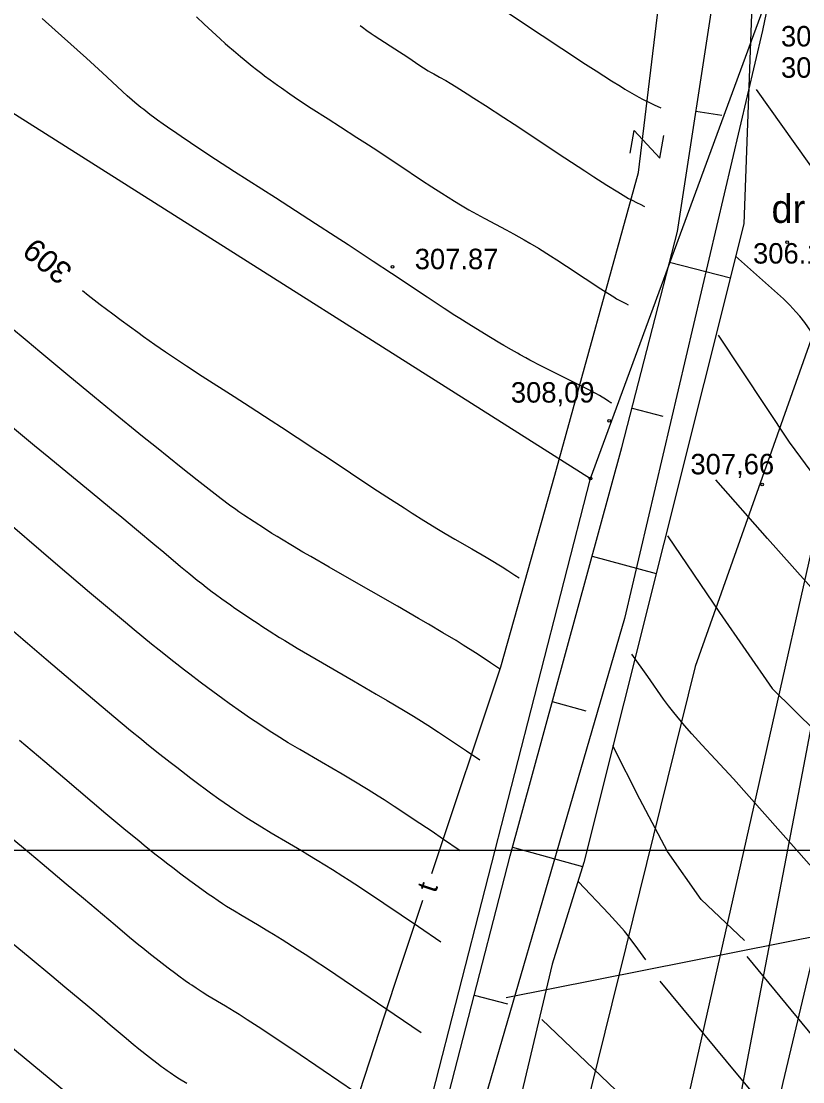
# Model space of a CAD drawing. Extents: x 7477803 to 7478145, y 5500698 to 5500984.
# Drawn here: x 7478000.31 to 7478026.29, y 5500742.3 to 5500777.55 of the extents above; entities that cross this region are included whole.
import ezdxf

# ---------------------------------------------------------------- set-up
doc = ezdxf.new("R2010")
doc.units = 0
for name, color, linetype in [('203-Punkt załamania granicy działki nie stabilizowany', 7, 'Continuous'), ('e_Proj', 7, 'Continuous'), ('eNN', 7, 'Continuous'), ('gr_dzialki', 7, 'Continuous'), ('gr_klasy', 7, 'Continuous'), ('gr_uzytek', 7, 'Continuous'), ('k', 7, 'Continuous'), ('k_rzedne', 7, 'Continuous'), ('opis_uzytek', 7, 'Continuous'), ('pkt_wys', 7, 'Continuous'), ('przehaczenie', 7, 'Continuous'), ('robocza49', 7, 'Continuous'), ('rowy', 7, 'Continuous'), ('skarp_wypel', 7, 'Continuous'), ('skarpa_gora', 7, 'Continuous'), ('t', 7, 'Continuous'), ('t_opisy', 7, 'Continuous'), ('w', 7, 'Continuous'), ('warst_ciagla', 7, 'Continuous'), ('warst_opis', 7, 'Continuous'), ('warst_pogrub', 7, 'Continuous'), ('warst_przeryw', 7, 'Continuous')]:
    doc.layers.add(name, color=color, linetype=linetype)

# ---------------------------------------------------------------- blocks, each defined once
blk = doc.blocks.new('203')
blk.add_circle((0, 0), 0.045)
blk = doc.blocks.new('140')
at = {"layer": 'pkt_wys'}
blk.add_circle((0, 0), 0.045, dxfattribs=at)
blk.add_circle((0, 0), 0.045, dxfattribs=at)
blk = doc.blocks.new('991_5_1')
at = {"layer": 'przehaczenie'}
blk.add_lwpolyline([(-0.38, 0.5), (0.38, 0.5), (-0.38, -0.5), (0.38, -0.5)], dxfattribs=at)

msp = doc.modelspace()

# ---------------------------------------------------------------- linework, layer by layer
at = {"layer": 'e_Proj'}
msp.add_lwpolyline([(7478085.721, 5500828.46), (7478062.59, 5500828.394), (7478057.723, 5500828.457), (7478045.093, 5500816.16), (7478029.949, 5500801.309), (7478024.948, 5500777.245), (7478020.357, 5500757.697), (7478013.921, 5500735.554), (7478010.536, 5500720.256)], dxfattribs=at)
at = {"layer": 'eNN'}
msp.add_lwpolyline([(7478021.084, 5500721.798), (7478022.348, 5500727.709), (7478025.636, 5500742.267), (7478028.577, 5500754.673), (7478031.014, 5500765.159)], dxfattribs=at)
at = {"layer": 'gr_dzialki'}
for points in [[(7477965.87, 5500796.14), (7478019.23, 5500762.35)], [(7478009.6, 5500724.81), (7478019.23, 5500762.35)]]:
    msp.add_lwpolyline(points, dxfattribs=at)
at = {"layer": 'gr_klasy'}
for points in [[(7478019.23, 5500762.35), (7478025.09, 5500778.3)], [(7478009.6, 5500724.81), (7478019.23, 5500762.35)]]:
    msp.add_lwpolyline(points, dxfattribs=at)
at = {"layer": 'gr_uzytek'}
msp.add_lwpolyline([(7478030.57, 5500778.31), (7478022.71, 5500756.1), (7478014.63, 5500723.4), (7478013.163, 5500719.326)], dxfattribs=at)
at = {"layer": 'k'}
msp.add_line((7478029.096, 5500771.195), (7478020.147, 5500731.456), dxfattribs=at)
at = {"layer": 'robocza49'}
msp.add_line((7478000, 5500750), (7478063.045, 5500750), dxfattribs=at)
at = {"layer": 'rowy'}
msp.add_line((7478016.422, 5500745.094), (7478036.731, 5500749.125), dxfattribs=at)
at = {"layer": 'skarp_wypel'}
for p, q in [((7478022.735, 5500774.561), (7478023.594, 5500774.428)), ((7478021.857, 5500769.544), (7478023.88, 5500769.024)), ((7478020.61, 5500764.687), (7478021.635, 5500764.423)), ((7478019.286, 5500759.771), (7478021.412, 5500759.188)), ((7478017.96, 5500754.933), (7478019.077, 5500754.627)), ((7478016.635, 5500750.095), (7478018.966, 5500749.456)), ((7478015.364, 5500745.175), (7478016.47, 5500744.89))]:
    msp.add_line(p, q, dxfattribs=at)
at = {"layer": 'skarpa_gora'}
for points in [[(7478024.881, 5500786.965), (7478024.924, 5500787.202), (7478024.325, 5500770.813), (7478019.007, 5500749.589), (7478017.956, 5500746.211), (7478015.629, 5500736.387), (7478013.818, 5500729.802), (7478010.366, 5500720.316)], [(7478008.529, 5500720.966), (7478013.614, 5500738.374), (7478016.556, 5500749.806), (7478020.275, 5500763.382), (7478022.118, 5500770.559), (7478023.375, 5500778.71), (7478024.881, 5500786.965)]]:
    msp.add_lwpolyline(points, dxfattribs=at)
at = {"layer": 't'}
for points in [[(7478013.952, 5500749.22), (7478016.25, 5500756.094), (7478018.043, 5500762.466), (7478020.822, 5500772.519), (7478021.714, 5500779.89), (7478022.482, 5500781.51), (7478023.011, 5500782.131), (7478024.071, 5500782.682), (7478025.381, 5500782.734), (7478026.491, 5500782.665), (7478029.072, 5500781.778), (7478030.398, 5500780.809)], [(7478005.519, 5500722.031), (7478006.224, 5500724.533), (7478008.555, 5500732.765), (7478012.721, 5500745.54), (7478013.655, 5500748.332)]]:
    msp.add_lwpolyline(points, dxfattribs=at)
at = {"layer": 'w'}
msp.add_lwpolyline([(7478028.928, 5500766.534), (7478026.087, 5500751.628), (7478024.78, 5500744.808), (7478022.827, 5500734.611), (7478021.568, 5500727.759), (7478020.307, 5500723.115), (7478018.729, 5500717.357)], dxfattribs=at)
at = {"layer": 'warst_ciagla'}
for points in [[(7478019.944, 5500764.854), (7478019.908, 5500764.872), (7478019.84, 5500764.912), (7478019.726, 5500764.987), (7478019.614, 5500765.057), (7478019.527, 5500765.108), (7478019.406, 5500765.175), (7478019.192, 5500765.288), (7478019.061, 5500765.355), (7478018.837, 5500765.469), (7478018.485, 5500765.645), (7478018.285, 5500765.744), (7478017.842, 5500765.965), (7478017.6, 5500766.088), (7478017.213, 5500766.29), (7478017.078, 5500766.362), (7478016.894, 5500766.464), (7478016.801, 5500766.516), (7478016.609, 5500766.624), (7478016.347, 5500766.776), (7478016.212, 5500766.855), (7478015.901, 5500767.04), (7478015.413, 5500767.339), (7478015.189, 5500767.479), (7478014.881, 5500767.673), (7478014.724, 5500767.774), (7478014.363, 5500768.008), (7478013.801, 5500768.377), (7478012.619, 5500769.164), (7478012.006, 5500769.57), (7478011.17, 5500770.119), (7478010.744, 5500770.397), (7478010.094, 5500770.819), (7478009.208, 5500771.39), (7478008.756, 5500771.679), (7478007.4, 5500772.546), (7478006.76, 5500772.959), (7478006.173, 5500773.345), (7478005.93, 5500773.508), (7478005.624, 5500773.716), (7478005.478, 5500773.816), (7478005.169, 5500774.033), (7478005.023, 5500774.136), (7478004.839, 5500774.269), (7478004.751, 5500774.334), (7478004.584, 5500774.458), (7478004.378, 5500774.616), (7478004.283, 5500774.69), (7478004.086, 5500774.85), (7478003.997, 5500774.925), (7478003.831, 5500775.07), (7478003.672, 5500775.215), (7478003.328, 5500775.538), (7478003.006, 5500775.837), (7478002.474, 5500776.324), (7478002.165, 5500776.605), (7478001.441, 5500777.257), (7478001.004, 5500777.649)], [(7478011.578, 5500777.414), (7478011.647, 5500777.357), (7478011.792, 5500777.247), (7478011.94, 5500777.143), (7478012.038, 5500777.079), (7478012.223, 5500776.96), (7478012.722, 5500776.638), (7478013.155, 5500776.354), (7478013.557, 5500776.087), (7478013.681, 5500776.007), (7478013.838, 5500775.909), (7478013.912, 5500775.863), (7478014.019, 5500775.8), (7478014.152, 5500775.724), (7478014.215, 5500775.69), (7478014.417, 5500775.582), (7478014.564, 5500775.497), (7478014.768, 5500775.372), (7478015.133, 5500775.142), (7478015.356, 5500775), (7478015.74, 5500774.751), (7478016.346, 5500774.355), (7478016.688, 5500774.129), (7478018.38, 5500773.01), (7478019.042, 5500772.576), (7478019.343, 5500772.38), (7478019.769, 5500772.107), (7478020.133, 5500771.878), (7478020.314, 5500771.769), (7478020.497, 5500771.665), (7478020.589, 5500771.614), (7478020.778, 5500771.515), (7478020.875, 5500771.468), (7478021.023, 5500771.399)], [(7478037.23, 5500752.292), (7478035.533, 5500754.662), (7478033.837, 5500757.031), (7478030.597, 5500761.551), (7478027.356, 5500766.07), (7478026.557, 5500767.248), (7478026.349, 5500767.535), (7478026.186, 5500767.744), (7478026.058, 5500767.896), (7478025.857, 5500768.115), (7478025.642, 5500768.321), (7478024.845, 5500769.032), (7478024.048, 5500769.742)], [(7478002.344, 5500768.601), (7478002.53, 5500768.451), (7478002.929, 5500768.14), (7478003.348, 5500767.822), (7478003.63, 5500767.612), (7478004.181, 5500767.211), (7478004.377, 5500767.071), (7478004.751, 5500766.807), (7478005.107, 5500766.56), (7478005.338, 5500766.403), (7478005.797, 5500766.097), (7478006.321, 5500765.756), (7478007.383, 5500765.076), (7478007.913, 5500764.736), (7478008.613, 5500764.283), (7478008.961, 5500764.056), (7478009.481, 5500763.717), (7478010.168, 5500763.264), (7478010.509, 5500763.037), (7478011.996, 5500762.046), (7478012.455, 5500761.745), (7478013.031, 5500761.372), (7478013.303, 5500761.199), (7478013.692, 5500760.954), (7478014.175, 5500760.658), (7478014.401, 5500760.523), (7478014.72, 5500760.335), (7478015.286, 5500760.009), (7478015.764, 5500759.733), (7478015.986, 5500759.602), (7478016.187, 5500759.481), (7478016.297, 5500759.413), (7478016.487, 5500759.291), (7478016.718, 5500759.137), (7478016.853, 5500759.045)], [(7478034.133, 5500748.935), (7478033.014, 5500750.407), (7478031.894, 5500751.88), (7478029.426, 5500755.195), (7478028.164, 5500756.83), (7478027.512, 5500757.63), (7478026.839, 5500758.413), (7478025.117, 5500760.359), (7478023.396, 5500762.305)], [(7477999.108, 5500758.074), (7478001.137, 5500756.346), (7478002.244, 5500755.403), (7478002.818, 5500754.917), (7478003.388, 5500754.439), (7478003.668, 5500754.206), (7478003.943, 5500753.979), (7478004.301, 5500753.687), (7478004.476, 5500753.545), (7478004.819, 5500753.269), (7478005.262, 5500752.919), (7478005.477, 5500752.751), (7478005.944, 5500752.393), (7478006.169, 5500752.223), (7478006.461, 5500752.006), (7478006.604, 5500751.902), (7478006.881, 5500751.703), (7478007.236, 5500751.454), (7478007.406, 5500751.337), (7478007.775, 5500751.092), (7478007.951, 5500750.979), (7478008.289, 5500750.77), (7478008.611, 5500750.576), (7478009.225, 5500750.217), (7478009.627, 5500749.979), (7478009.831, 5500749.857), (7478010.148, 5500749.664), (7478010.658, 5500749.348), (7478011.001, 5500749.131), (7478011.206, 5500748.999), (7478011.581, 5500748.753), (7478012.364, 5500748.231), (7478013.508, 5500747.455), (7478014.251, 5500746.948)], [(7478028.138, 5500747.675), (7478026.06, 5500750.018), (7478023.983, 5500752.362), (7478023.386, 5500753.014), (7478022.933, 5500753.498), (7478022.597, 5500753.865), (7478022.351, 5500754.144), (7478021.994, 5500754.573), (7478021.824, 5500754.794), (7478021.659, 5500755.019), (7478021.133, 5500755.764), (7478020.607, 5500756.509)], [(7478024.344, 5500746.993), (7478022.912, 5500748.355), (7478021.785, 5500749.947), (7478020.867, 5500751.696), (7478019.967, 5500753.459)], [(7478011.649, 5500734.85), (7478008.326, 5500737.122), (7478007.088, 5500737.967), (7478005.947, 5500738.743), (7478005.498, 5500739.046), (7478004.968, 5500739.4), (7478004.67, 5500739.589), (7478004.599, 5500739.636), (7478004.494, 5500739.711), (7478004.438, 5500739.753), (7478004.348, 5500739.823), (7478004.219, 5500739.926), (7478004.15, 5500739.983), (7478003.614, 5500740.431), (7478002.063, 5500741.714), (7477999.307, 5500743.984), (7477995.668, 5500746.981), (7477994.123, 5500748.258), (7477993.37, 5500748.883), (7477992.227, 5500749.834), (7477990.687, 5500751.121), (7477990, 5500751.698), (7477989.207, 5500752.369)], [(7478011.909, 5500741.611), (7478010.345, 5500742.676), (7478009.335, 5500743.36), (7478008.886, 5500743.661), (7478008.303, 5500744.046), (7478007.823, 5500744.355), (7478007.553, 5500744.527), (7478007.39, 5500744.628), (7478007.096, 5500744.808), (7478006.514, 5500745.157), (7478006.322, 5500745.277), (7478006.222, 5500745.34), (7478006.12, 5500745.408), (7478005.979, 5500745.503), (7478005.906, 5500745.553), (7478005.757, 5500745.657), (7478005.549, 5500745.806), (7478005.442, 5500745.885), (7478005.191, 5500746.073), (7478004.792, 5500746.381), (7478004.605, 5500746.529), (7478004.348, 5500746.735), (7478004.216, 5500746.842), (7478003.909, 5500747.094), (7478003.426, 5500747.498), (7478002.375, 5500748.389), (7478001.807, 5500748.869), (7478001.005, 5500749.543), (7478000.585, 5500749.894), (7477999.932, 5500750.439)]]:
    msp.add_lwpolyline(points, dxfattribs=at)
at = {"layer": 'warst_pogrub'}
for points in [[(7477999.886, 5500764.173), (7478000.754, 5500763.45), (7478001.231, 5500763.056), (7478002.043, 5500762.39), (7478002.602, 5500761.932), (7478003.311, 5500761.347), (7478003.65, 5500761.067), (7478004.138, 5500760.66), (7478004.752, 5500760.145), (7478005.044, 5500759.9), (7478005.602, 5500759.429), (7478005.879, 5500759.199), (7478006.161, 5500758.971), (7478006.306, 5500758.857), (7478006.454, 5500758.742), (7478006.656, 5500758.588), (7478006.76, 5500758.511), (7478006.971, 5500758.356), (7478007.262, 5500758.148), (7478007.412, 5500758.043), (7478007.757, 5500757.806), (7478007.935, 5500757.687), (7478008.178, 5500757.527), (7478008.301, 5500757.447), (7478008.553, 5500757.286), (7478008.897, 5500757.07), (7478009.073, 5500756.961), (7478009.479, 5500756.715), (7478009.686, 5500756.591), (7478010.108, 5500756.344), (7478011.354, 5500755.626), (7478012.11, 5500755.187), (7478012.472, 5500754.973), (7478013.013, 5500754.65), (7478013.346, 5500754.449), (7478013.526, 5500754.337), (7478013.828, 5500754.146), (7478014.181, 5500753.918), (7478014.382, 5500753.785), (7478014.844, 5500753.478), (7478015.108, 5500753.299), (7478015.552, 5500752.996)], [(7478021.067, 5500746.354), (7478020.717, 5500746.833), (7478020.54, 5500747.07), (7478020.448, 5500747.187), (7478020.355, 5500747.302), (7478020.173, 5500747.514), (7478019.843, 5500747.877), (7478018.828, 5500748.943)], [(7478027.721, 5500738.329), (7478026.825, 5500739.318), (7478026.384, 5500739.82), (7478025.952, 5500740.329), (7478023.747, 5500742.986), (7478021.542, 5500745.643)]]:
    msp.add_lwpolyline(points, dxfattribs=at)
at = {"layer": 'warst_przeryw'}
for points in [[(7478016.304, 5500777.954), (7478017.624, 5500777.075), (7478018.278, 5500776.643), (7478019.06, 5500776.131), (7478019.418, 5500775.9), (7478019.928, 5500775.574), (7478020.223, 5500775.39), (7478020.371, 5500775.299), (7478020.598, 5500775.165), (7478020.834, 5500775.032), (7478020.957, 5500774.967), (7478021.214, 5500774.836), (7478021.35, 5500774.77), (7478021.563, 5500774.672)], [(7478006.131, 5500777.702), (7478006.391, 5500777.454), (7478006.652, 5500777.21), (7478006.783, 5500777.089), (7478006.915, 5500776.97), (7478007.092, 5500776.813), (7478007.18, 5500776.735), (7478007.358, 5500776.581), (7478007.597, 5500776.38), (7478007.717, 5500776.281), (7478007.988, 5500776.061), (7478008.125, 5500775.953), (7478008.308, 5500775.812), (7478008.399, 5500775.742), (7478008.584, 5500775.604), (7478008.831, 5500775.423), (7478008.955, 5500775.334), (7478009.236, 5500775.138), (7478009.378, 5500775.042), (7478009.662, 5500774.853), (7478009.946, 5500774.668), (7478010.51, 5500774.307), (7478010.925, 5500774.04), (7478011.467, 5500773.691), (7478011.733, 5500773.518), (7478012.125, 5500773.262), (7478012.636, 5500772.925), (7478012.887, 5500772.759), (7478013.614, 5500772.275), (7478013.96, 5500772.047), (7478014.291, 5500771.834), (7478014.708, 5500771.573), (7478014.906, 5500771.452), (7478015.191, 5500771.283), (7478015.312, 5500771.213), (7478015.47, 5500771.124), (7478015.546, 5500771.081), (7478015.714, 5500770.99), (7478016.425, 5500770.62), (7478016.673, 5500770.485), (7478017.025, 5500770.286), (7478017.209, 5500770.177), (7478017.496, 5500770.004), (7478017.898, 5500769.753), (7478018.108, 5500769.619), (7478018.43, 5500769.409), (7478019.053, 5500768.999), (7478019.574, 5500768.658), (7478019.805, 5500768.51), (7478020.001, 5500768.386), (7478020.099, 5500768.327), (7478020.249, 5500768.243), (7478020.403, 5500768.164), (7478020.484, 5500768.127)], [(7478024.737, 5500775.282), (7478028.185, 5500770.437), (7478030.56, 5500764.878), (7478033.801, 5500759.808), (7478037.328, 5500754.935)], [(7478016.203, 5500756.021), (7478015.91, 5500756.22), (7478015.732, 5500756.34), (7478015.41, 5500756.552), (7478015, 5500756.815), (7478014.761, 5500756.963), (7478014.326, 5500757.225), (7478013.846, 5500757.508), (7478013.517, 5500757.7), (7478012.813, 5500758.106), (7478011.062, 5500759.106), (7478010.54, 5500759.405), (7478009.935, 5500759.754), (7478009.671, 5500759.908), (7478009.326, 5500760.111), (7478008.956, 5500760.331), (7478008.81, 5500760.42), (7478008.637, 5500760.528), (7478008.389, 5500760.691), (7478008.05, 5500760.914), (7478007.705, 5500761.137), (7478007.539, 5500761.245), (7478007.436, 5500761.316), (7478007.233, 5500761.463), (7478006.953, 5500761.674), (7478006.455, 5500762.061), (7478006.151, 5500762.301), (7478005.629, 5500762.717), (7478004.806, 5500763.377), (7478004.34, 5500763.753), (7478003.307, 5500764.593), (7478002.746, 5500765.052), (7478001.86, 5500765.782), (7478000.93, 5500766.557), (7478000.503, 5500766.915), (7477999.922, 5500767.405)], [(7478023.475, 5500767.116), (7478025.833, 5500763.558), (7478028.366, 5500760.127), (7478030.951, 5500756.73), (7478033.451, 5500753.27)], [(7478014.902, 5500749.972), (7478014.308, 5500750.377), (7478013.962, 5500750.612), (7478013.373, 5500751.008), (7478013.125, 5500751.174), (7478012.704, 5500751.45), (7478012.366, 5500751.668), (7478012.174, 5500751.79), (7478011.836, 5500751.999), (7478011.31, 5500752.319), (7478010.971, 5500752.522), (7478010.289, 5500752.921), (7478009.567, 5500753.341), (7478009.184, 5500753.569), (7478008.785, 5500753.814), (7478008.578, 5500753.945), (7478008.367, 5500754.082), (7478008.079, 5500754.273), (7478007.931, 5500754.373), (7478007.63, 5500754.58), (7478007.216, 5500754.873), (7478007.004, 5500755.026), (7478006.512, 5500755.389), (7478006.259, 5500755.58), (7478005.914, 5500755.843), (7478005.739, 5500755.978), (7478005.382, 5500756.257), (7478004.893, 5500756.646), (7478004.643, 5500756.847), (7478004.067, 5500757.318), (7478003.772, 5500757.562), (7478003.175, 5500758.061), (7478002.58, 5500758.564), (7478001.446, 5500759.531), (7477999.454, 5500761.229)], [(7478021.789, 5500760.44), (7478023.517, 5500757.897), (7478025.268, 5500755.372), (7478027.456, 5500753.206), (7478029.913, 5500751.319)], [(7478013.601, 5500743.923), (7478012.708, 5500744.533), (7478011.354, 5500745.454), (7478010.458, 5500746.057), (7478010.046, 5500746.33), (7478009.829, 5500746.472), (7478009.48, 5500746.697), (7478008.985, 5500747.01), (7478008.692, 5500747.192), (7478008.509, 5500747.304), (7478008.161, 5500747.513), (7478007.657, 5500747.81), (7478007.401, 5500747.963), (7478007.136, 5500748.128), (7478006.999, 5500748.216), (7478006.857, 5500748.31), (7478006.661, 5500748.441), (7478006.56, 5500748.511), (7478006.353, 5500748.656), (7478006.065, 5500748.863), (7478005.916, 5500748.972), (7478005.567, 5500749.233), (7478005.387, 5500749.371), (7478005.14, 5500749.562), (7478005.013, 5500749.661), (7478004.754, 5500749.865), (7478004.398, 5500750.152), (7478004.214, 5500750.301), (7478003.789, 5500750.65), (7478003.122, 5500751.208), (7478002.666, 5500751.593), (7478001.756, 5500752.368), (7478001.095, 5500752.929), (7478000.252, 5500753.642)], [(7478005.814, 5500742.237), (7478005.567, 5500742.388), (7478005.446, 5500742.464), (7478005.253, 5500742.594), (7478005.161, 5500742.658), (7478005.034, 5500742.75), (7478004.968, 5500742.798), (7478004.814, 5500742.913), (7478004.57, 5500743.102), (7478004.217, 5500743.384), (7478004.029, 5500743.539), (7478003.73, 5500743.789), (7478003.267, 5500744.18), (7478002.994, 5500744.41), (7478002.519, 5500744.809), (7478001.759, 5500745.443), (7478001.324, 5500745.804), (7478000.605, 5500746.4), (7477999.52, 5500747.297)], [(7478034.445, 5500735.155), (7478031.806, 5500737.855), (7478029.286, 5500740.667), (7478026.843, 5500743.549), (7478024.438, 5500746.459)], [(7478032.47, 5500728.495), (7478028.924, 5500732.62), (7478025.371, 5500736.739), (7478021.544, 5500740.607), (7478017.614, 5500744.368)]]:
    msp.add_lwpolyline(points, dxfattribs=at)

# ---------------------------------------------------------------- block references
at = {"layer": '203-Punkt załamania granicy działki nie stabilizowany'}
msp.add_blockref('203', (7478019.23, 5500762.35), dxfattribs=at)
at = {"layer": 'pkt_wys', "rotation": 0.0626175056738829}
for p in [(7478025.768, 5500770.212), (7478012.651, 5500769.385), (7478019.847, 5500764.265), (7478024.931, 5500762.153)]:
    msp.add_blockref('140', p, dxfattribs=at)
at = {"layer": 'przehaczenie', "rotation": 80.33922208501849}
msp.add_blockref('991_5_1', (7478021.105, 5500773.463), dxfattribs=at)

# ---------------------------------------------------------------- texts
at = {"layer": 'k_rzedne'}
for s, p in [('305.57', (7478025.561, 5500776.714)), ('303.49', (7478025.562, 5500775.674))]:
    msp.add_text(s, height=0.68, rotation=0.0626, dxfattribs=at).set_placement(p)
at = {"layer": 'opis_uzytek'}
msp.add_text('dr', height=0.94, dxfattribs=at).set_placement((7478025.247, 5500770.849))
at = {"layer": 'pkt_wys'}
for s, p in [('306.13', (7478024.633, 5500769.496)), ('307.87', (7478013.388, 5500769.308)), ('308,09', (7478016.583, 5500764.874)), ('307,66', (7478022.552, 5500762.489))]:
    msp.add_text(s, height=0.68, rotation=0.0626, dxfattribs=at).set_placement(p)
at = {"layer": 't_opisy'}
msp.add_text('t', height=0.68, rotation=71.5137, dxfattribs=at).set_placement((7478014.085, 5500748.546))
at = {"layer": 'warst_opis'}
msp.add_text('309', height=0.75, rotation=140.1952, dxfattribs=at).set_placement((7478002.062, 5500769.325))

doc.saveas('drawing.dxf')
